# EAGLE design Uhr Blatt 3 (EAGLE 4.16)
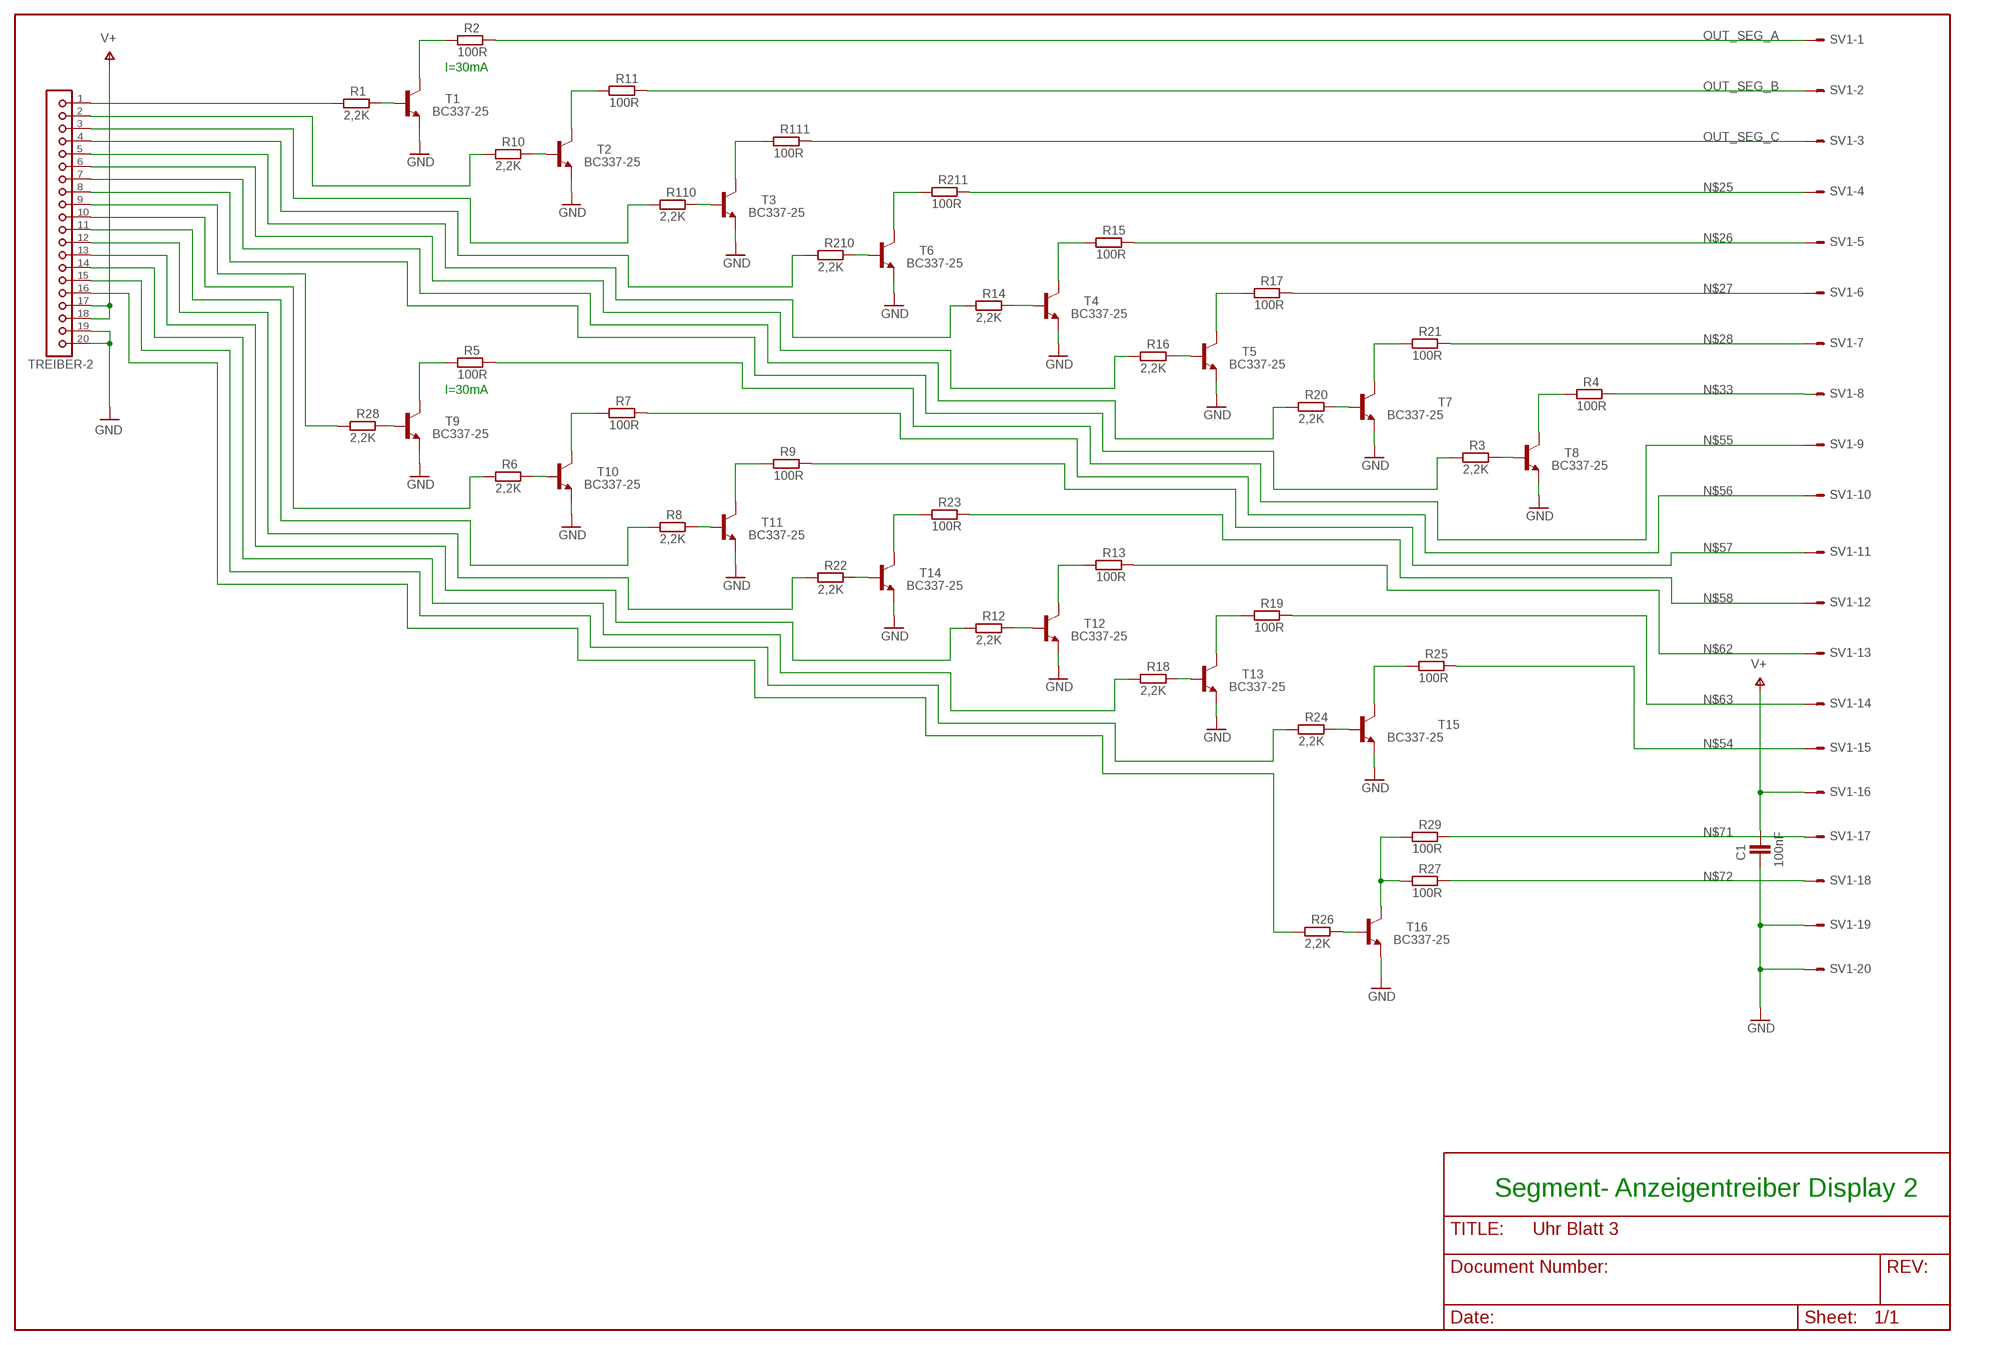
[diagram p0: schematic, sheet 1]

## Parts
C1  100nF  C-EU050-024X044  [C050-024X044]
R1  2,2K  R-EU_0207/10  [0207/10]
R2  100R  R-EU_0207/10  [0207/10]
R3  2,2K  R-EU_0207/10  [0207/10]
R4  100R  R-EU_0207/10  [0207/10]
R5  100R  R-EU_0207/10  [0207/10]
R6  2,2K  R-EU_0207/10  [0207/10]
R7  100R  R-EU_0207/10  [0207/10]
R8  2,2K  R-EU_0207/10  [0207/10]
R9  100R  R-EU_0207/10  [0207/10]
R10  2,2K  R-EU_0207/10  [0207/10]
R11  100R  R-EU_0207/10  [0207/10]
R12  2,2K  R-EU_0207/10  [0207/10]
R13  100R  R-EU_0207/10  [0207/10]
R14  2,2K  R-EU_0207/10  [0207/10]
R15  100R  R-EU_0207/10  [0207/10]
R16  2,2K  R-EU_0207/10  [0207/10]
R17  100R  R-EU_0207/10  [0207/10]
R18  2,2K  R-EU_0207/10  [0207/10]
R19  100R  R-EU_0207/10  [0207/10]
R20  2,2K  R-EU_0207/10  [0207/10]
R21  100R  R-EU_0207/10  [0207/10]
R22  2,2K  R-EU_0207/10  [0207/10]
R23  100R  R-EU_0207/10  [0207/10]
R24  2,2K  R-EU_0207/10  [0207/10]
R25  100R  R-EU_0207/10  [0207/10]
R26  2,2K  R-EU_0207/10  [0207/10]
R27  100R  R-EU_0207/10  [0207/10]
R28  2,2K  R-EU_0207/10  [0207/10]
R29  100R  R-EU_0207/10  [0207/10]
R110  2,2K  R-EU_0207/10  [0207/10]
R111  100R  R-EU_0207/10  [0207/10]
R210  2,2K  R-EU_0207/10  [0207/10]
R211  100R  R-EU_0207/10  [0207/10]
SV1  ML20E  [ML20]
T1  BC337-25  [TO92]
T2  BC337-25  [TO92]
T3  BC337-25  [TO92]
T4  BC337-25  [TO92]
T5  BC337-25  [TO92]
T6  BC337-25  [TO92]
T7  BC337-25  [TO92]
T8  BC337-25  [TO92]
T9  BC337-25  [TO92]
T10  BC337-25  [TO92]
T11  BC337-25  [TO92]
T12  BC337-25  [TO92]
T13  BC337-25  [TO92]
T14  BC337-25  [TO92]
T15  BC337-25  [TO92]
T16  BC337-25  [TO92]
TREIBER-2  JU20  [JU20]

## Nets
GND: C1.1 SV1.19 SV1.20 T1.1(E) T2.1(E) T3.1(E) T4.1(E) T5.1(E) T6.1(E) T7.1(E) T8.1(E) T9.1(E) T10.1(E) T11.1(E) T12.1(E) T13.1(E) T14.1(E) T15.1(E) T16.1(E) TREIBER-2.19 TREIBER-2.20
N$1: R2.1 T1.3(C)
N$2: R1.2 T1.2(B)
N$3: R11.1 T2.3(C)
N$4: R10.2 T2.2(B)
N$5: R111.1 T3.3(C)
N$6: R110.2 T3.2(B)
N$7: R15.1 T4.3(C)
N$8: R14.2 T4.2(B)
N$9: R17.1 T5.3(C)
N$10: R16.2 T5.2(B)
N$11: R211.1 T6.3(C)
N$12: R210.2 T6.2(B)
N$13: R21.1 T7.3(C)
N$14: R20.2 T7.2(B)
N$25: R211.2 SV1.4
N$26: R15.2 SV1.5
N$27: R17.2 SV1.6
N$28: R21.2 SV1.7
N$29: R4.1 T8.3(C)
N$30: R3.2 T8.2(B)
N$31: R5.1 T9.3(C)
N$33: R4.2 SV1.8
N$34: R7.1 T10.3(C)
N$35: R6.2 T10.2(B)
N$36: R9.1 T11.3(C)
N$37: R8.2 T11.2(B)
N$38: R13.1 T12.3(C)
N$39: R12.2 T12.2(B)
N$40: R19.1 T13.3(C)
N$41: R18.2 T13.2(B)
N$42: R23.1 T14.3(C)
N$43: R22.2 T14.2(B)
N$44: R25.1 T15.3(C)
N$45: R24.2 T15.2(B)
N$53: R28.2 T9.2(B)
N$54: R25.2 SV1.15
N$55: R5.2 SV1.9
N$56: R7.2 SV1.10
N$57: R9.2 SV1.11
N$58: R23.2 SV1.12
N$62: R13.2 SV1.13
N$63: R19.2 SV1.14
N$69: R26.2 T16.2(B)
N$70: R27.1 R29.1 T16.3(C)
N$71: R29.2 SV1.17
N$72: R27.2 SV1.18
OUT_SEG_A: R2.2 SV1.1
OUT_SEG_B: R11.2 SV1.2
OUT_SEG_C: R111.2 SV1.3
SEG_A: R1.1 TREIBER-2.1
SEG_B: R10.1 TREIBER-2.2
SEG_C: R110.1 TREIBER-2.3
SEG_D: R210.1 TREIBER-2.4
SEG_E+F: R26.1 TREIBER-2.16
SEG_G: R14.1 TREIBER-2.5
SEG_H: R16.1 TREIBER-2.6
SEG_I: R20.1 TREIBER-2.7
SEG_J: R3.1 TREIBER-2.8
SEG_K: R28.1 TREIBER-2.9
SEG_L: R6.1 TREIBER-2.10
SEG_M: R8.1 TREIBER-2.11
SEG_N: R22.1 TREIBER-2.12
SEG_O: R12.1 TREIBER-2.13
SEG_P: R18.1 TREIBER-2.14
SEG_X: R24.1 TREIBER-2.15
V+: C1.2 SV1.16 TREIBER-2.17 TREIBER-2.18

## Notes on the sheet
- I=30mA
- I=30mA
- Segment- | Anzeigentreiber Display 2

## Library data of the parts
C1 = rcl:C-EU: CAPACITOR, European symbol
R1-R29 R110 R111 R210 R211 = rcl:R-EU_: RESISTOR, European symbol
SV1 = con-harting-ml:ML20?E: HARTING
T1-T16 = transistor-npn:BC337*: NPN Transistor
TREIBER-2 = con-lsta:JU20: PIN HEADER

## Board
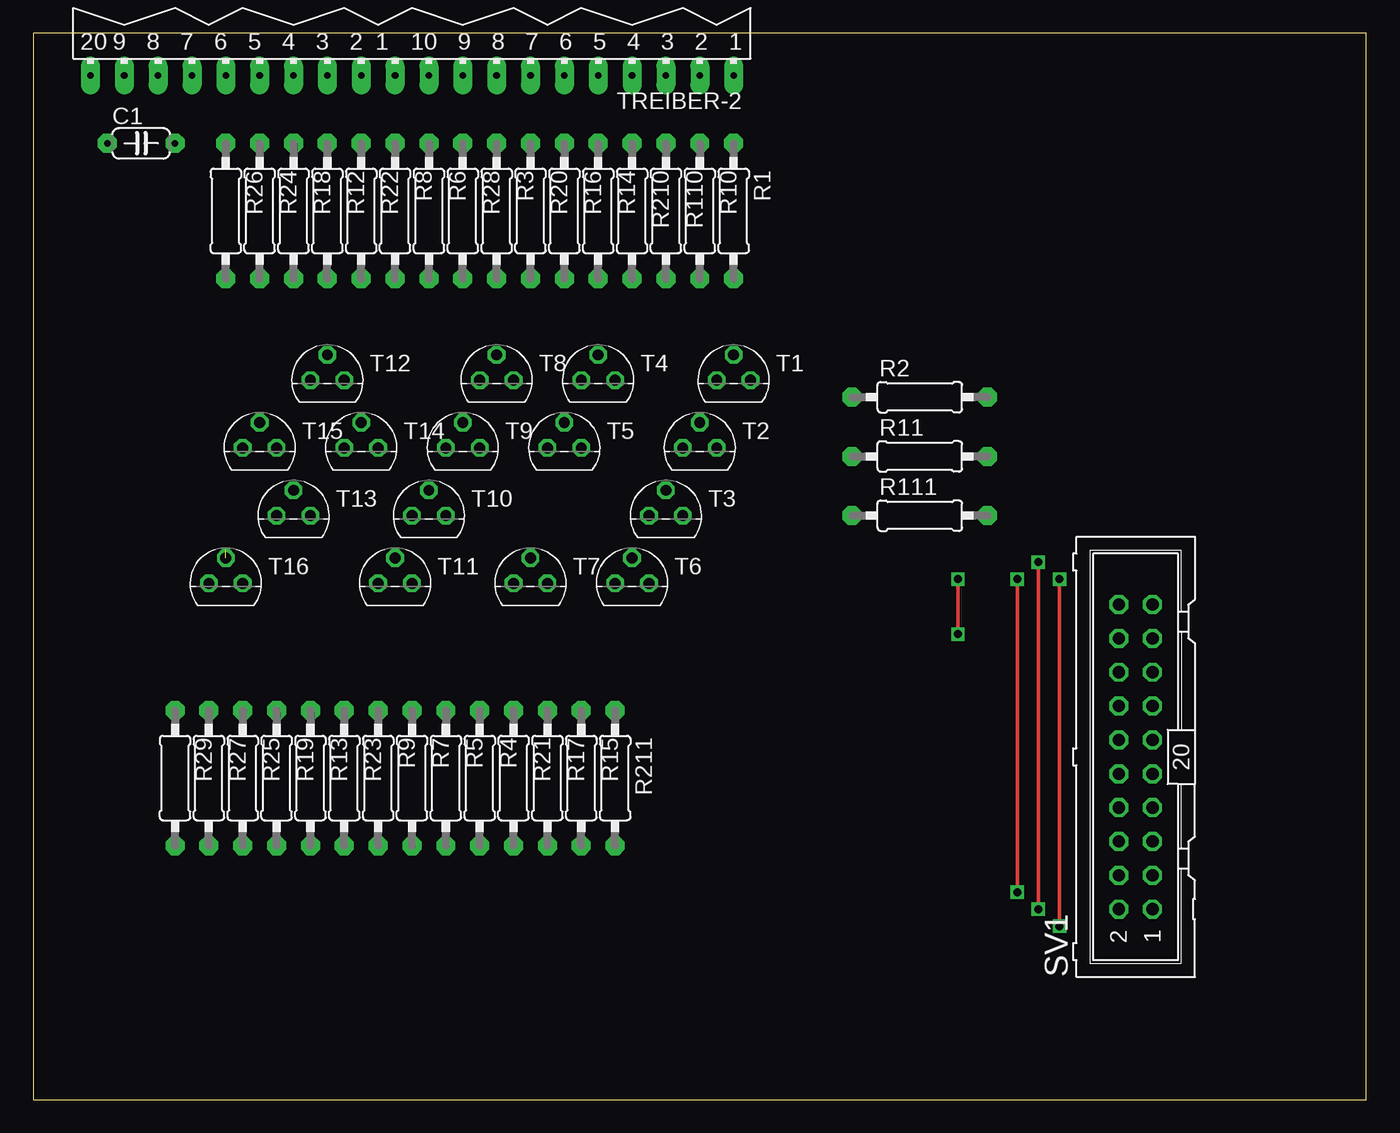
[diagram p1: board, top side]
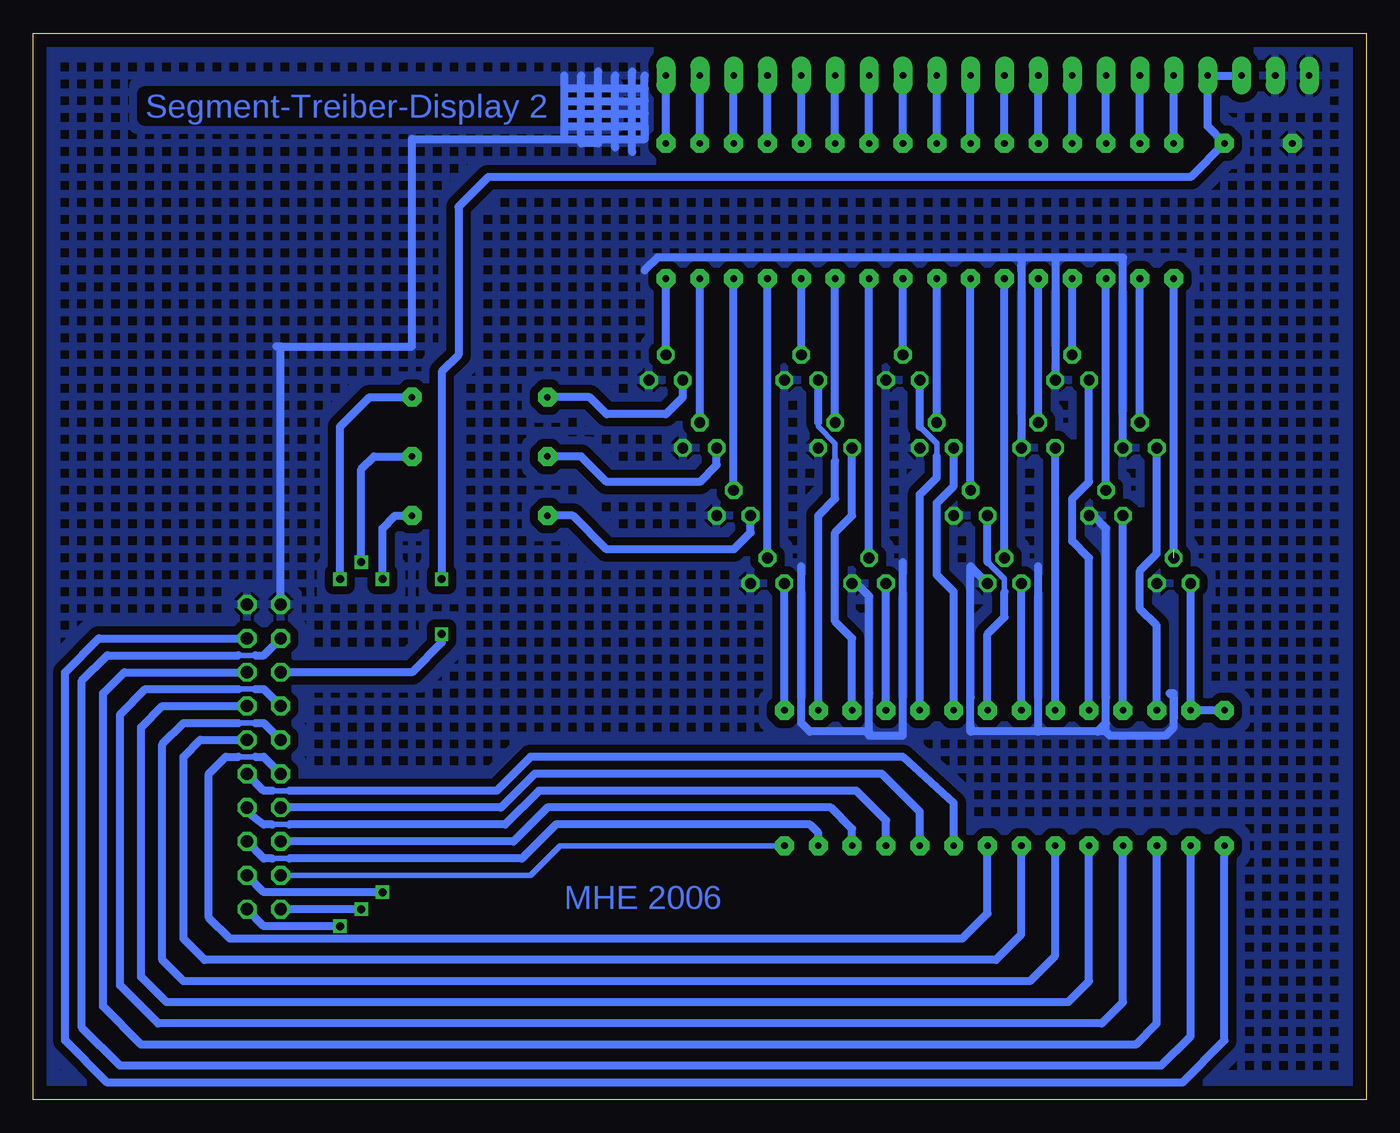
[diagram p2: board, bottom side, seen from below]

Size 100 x 80 mm. Coordinates in mm from the lower left corner, seen from the top.
Outline: 0,0 100,0 100,80 0,80 0,0
Copper layers (1*16): Top 0.035mm / dielectric 1.5mm / Bottom 0.035mm
Design rules "default": minimum track width 10mil, minimum drill 24mil, track to track 8mil, track to pad 8mil, pad to pad 8mil, via to via 8mil, smd to smd 8mil, copper to edge 40mil, drill to drill 8mil, minimum pad ring 10mil, minimum via ring 8mil, stop-mask expansion 4mil, vias tented up to drill 0mil, thermal gap 10mil

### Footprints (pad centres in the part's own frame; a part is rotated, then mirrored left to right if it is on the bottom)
C050-024X044 = drill 0.5 pad 1.422 octagon: 1 -2.54,0; 2 2.54,0
0207/10 = drill 0.5 pad 1.422 octagon: 1 -5.08,0; 2 5.08,0
ML20 = drill 0.914 octagon: 1 -11.43,-1.27; 2 -11.43,1.27; 3 -8.89,-1.27; 4 -8.89,1.27; 5 -6.35,-1.27; 6 -6.35,1.27; 7 -3.81,-1.27; 8 -3.81,1.27; 9 -1.27,-1.27; 10 -1.27,1.27; 11 1.27,-1.27; 12 1.27,1.27; 13 3.81,-1.27; 14 3.81,1.27; 15 6.35,-1.27; 16 6.35,1.27; 17 8.89,-1.27; 18 8.89,1.27; 19 11.43,-1.27; 20 11.43,1.27
TO92 = drill 0.813 octagon: 1 1.27,0; 2 0,1.905; 3 -1.27,0
JU20 = drill 0.5 pad 1.422 long: 1 -24.13,0; 2 -21.59,0; 3 -19.05,0; 4 -16.51,0; 5 -13.97,0; 6 -11.43,0; 7 -8.89,0; 8 -6.35,0; 9 -3.81,0; 10 -1.27,0; 11 1.27,0; 12 3.81,0; 13 6.35,0; 14 8.89,0; 15 11.43,0; 16 13.97,0; 17 16.51,0; 18 19.05,0; 19 21.59,0; 20 24.13,0

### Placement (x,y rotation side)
C1  8.09,71.75 0 top
R1  52.54,66.67 270 top
R2  66.51,52.7 0 top
R3  34.76,66.67 270 top
R4  33.49,24.12 270 top
R5  30.95,24.12 270 top
R6  29.68,66.67 270 top
R7  28.41,24.12 270 top
R8  27.14,66.67 270 top
R9  25.87,24.12 270 top
R10  50,66.67 270 top
R11  66.51,48.26 0 top
R12  22.06,66.67 270 top
R13  20.79,24.12 270 top
R14  42.38,66.67 270 top
R15  41.11,24.12 270 top
R16  39.84,66.67 270 top
R17  38.57,24.12 270 top
R18  19.52,66.67 270 top
R19  18.25,24.12 270 top
R20  37.3,66.67 270 top
R21  36.03,24.12 270 top
R22  24.6,66.67 270 top
R23  23.33,24.12 270 top
R24  16.98,66.67 270 top
R25  15.71,24.12 270 top
R26  14.44,66.67 270 top
R27  13.17,24.12 270 top
R28  32.22,66.67 270 top
R29  10.63,24.12 270 top
R110  47.46,66.67 270 top
R111  66.51,43.81 0 top
R210  44.92,66.67 270 top
R211  43.65,24.12 270 top
SV1  82.7,25.71 90 top
T1  52.54,53.97 0 top
T2  50,48.89 0 top
T3  47.46,43.81 0 top
T4  42.38,53.97 0 top
T5  39.84,48.89 0 top
T6  44.92,38.73 0 top
T7  37.3,38.73 0 top
T8  34.76,53.97 0 top
T9  32.22,48.89 0 top
T10  29.68,43.81 0 top
T11  27.14,38.73 0 top
T12  22.06,53.97 0 top
T13  19.52,43.81 0 top
T14  24.6,48.89 0 top
T15  16.98,48.89 0 top
T16  14.44,38.73 0 top
TREIBER-2  28.41,76.83 180 top

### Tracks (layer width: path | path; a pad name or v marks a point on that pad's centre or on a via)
GND
  Bottom 0.61: 14.44,30.16 14.44,30.47 14.76,30.47 14.44,30.16 | 14.44,30.16 14.44,28.57 | 42.38,40 42.38,28.25 41.74,27.62 37.3,27.62 | 25.87,62.23 T14.1 | 25.87,62.23 25.87,62.54 | 34.76,40.32 34.76,27.3 37.3,27.3 37.3,27.62 | 37.3,27.62 37.3,30.47 | 19.52,27.62 19.52,30.16 | 19.52,27.62 20.15,27.62 | 20.15,27.62 24.6,27.62 | 24.6,27.62 24.6,40 | 24.6,27.62 29.68,27.62 29.68,27.93 | 29.68,27.93 29.68,30.16 | T15.1 18.25,63.18 23.33,63.18 | 23.33,63.18 T12.1 | 23.33,63.18 25.87,63.18 | 25.87,63.18 25.87,62.23 | 14.44,30.16 14.44,27.93 15.08,27.3 19.2,27.3 19.52,27.62 | T13.1 20.47,43.81 19.52,42.86 19.52,28.25 20.15,27.62 | T11.1 29.68,40 29.68,27.93 | T7.1 38.25,38.73 37.3,37.78 37.3,27.62 | 54.13,73.02 54.13,72.07 58.89,72.07 | 54.13,73.02 54.13,73.97 | 54.13,73.97 54.13,74.92 | 54.13,74.92 54.13,75.88 | 54.13,75.88 54.13,76.83 | 25.87,63.18 53.17,63.18 54.13,62.23 | 60.16,72.07 71.59,72.07 71.59,56.51 81.43,56.51 | 60.16,72.07 58.89,72.07 | 81.43,56.51 81.75,56.51 | SV1.20 81.43,56.51 | 55.08,71.11 55.08,77.15 | 58.89,72.07 58.89,76.83 | 60.16,72.07 60.16,73.02 | 60.16,73.02 60.16,73.97 | 60.16,73.97 60.16,74.92 | 60.16,74.92 60.16,75.88 | 60.16,75.88 60.16,76.83 | 60.16,75.88 54.13,75.88 | 60.16,74.92 54.13,74.92 | 60.16,73.97 54.13,73.97 | 60.16,73.02 54.13,73.02 | 56.35,71.43 56.35,76.83 | 57.62,77.15 57.62,71.75 58.89,71.75 58.89,72.07
  pour Bottom (isolate 0.61, hatched): 0.47,0.63 0.47,79.37 99.85,79.37 99.85,0.63
N$1
  Bottom 0.61: T1.3 51.27,52.7 52.54,51.43 56.98,51.43 58.25,52.7 R2.1
N$2
  Bottom 0.61: T1.2 R1.2
N$3
  Bottom 0.61: T2.3 48.73,47.62 50,46.35 56.98,46.35 58.89,48.26 R11.1
N$4
  Bottom 0.61: T2.2 R10.2
N$5
  Bottom 0.61: T3.3 46.19,42.54 47.46,41.27 56.98,41.27 59.52,43.81 R111.1
N$6
  Bottom 0.61: T3.2 R110.2
N$7
  Bottom 0.406: 41.11,50.8 41.11,50.48 39.84,49.21 39.84,47.94
  Bottom 0.61: 41.11,51.11 T4.3 | 41.11,50.8 41.11,51.11 | 39.84,47.94 39.84,45.08 41.11,43.81 R15.1 | 41.11,51.11 41.11,54.29
N$8
  Bottom 0.61: T4.2 R14.2
N$9
  Bottom 0.61: T5.3 38.57,43.81 39.84,42.54 39.84,35.87 38.57,34.6 R17.1
N$10
  Bottom 0.61: T5.2 R16.2
N$11
  Bottom 0.61: R211.1 T6.3
N$12
  Bottom 0.61: T6.2 R210.2
N$13
  Bottom 0.61: R21.1 T7.3
N$14
  Bottom 0.61: T7.2 R20.2
N$25
  Bottom 0.406: R211.2 60.48,19.04 62.7,16.82 SV1.4
N$26
  Bottom 0.406: 80.8,18.09 82.07,18.09
  Bottom 0.61: R15.2 41.11,20 41.74,20.63 60.8,20.63 63.34,18.09 80.8,18.09 | 82.07,18.09 82.7,18.09 SV1.5
N$27
  Bottom 0.61: R17.2 38.57,20.31 40.16,21.9 61.43,21.9 63.97,19.36 SV1.6
N$28
  Bottom 0.406: 80.8,20.63 82.07,20.63
  Bottom 0.61: R21.2 36.03,20.95 38.25,23.17 62.06,23.17 64.61,20.63 80.8,20.63 | SV1.7 83.97,21.58 82.7,20.63 82.07,20.63
N$29
  Bottom 0.406: 33.49,50.48 32.22,49.21 32.22,48.26
  Bottom 0.61: 33.49,50.48 T8.3 | 32.22,48.26 32.22,46.67 33.49,45.4 R4.1
N$30
  Bottom 0.61: T8.2 R3.2
N$31
  Bottom 0.61: T9.3 30.95,46.03 32.22,44.76 32.22,39.37 30.95,38.1 R5.1
N$33
  Bottom 0.61: R4.2 33.49,21.58 36.35,24.44 62.38,24.44 64.92,21.9 SV1.8
N$34
  Bottom 0.406: 28.41,40.32 27.14,39.05 27.14,38.1
  Bottom 0.61: 28.41,40.32 T10.3 | 27.14,38.1 27.14,36.19 28.41,34.92 R7.1
N$35
  Bottom 0.61: T10.2 R6.2
N$36
  Bottom 0.61: R9.1 T11.3
N$37
  Bottom 0.61: T11.2 R8.2
N$38
  Bottom 0.61: T12.3 20.79,46.35 22.06,45.08 22.06,41.91 20.79,40.64 R13.1
N$39
  Bottom 0.61: T12.2 R12.2
N$40
  Bottom 0.61: R19.1 T13.3
N$41
  Bottom 0.61: T13.2 R18.2
N$42
  Bottom 0.61: R23.1 T14.3
N$43
  Bottom 0.61: T14.2 R22.2
N$44
  Bottom 0.61: T15.3 15.71,40.95 16.98,39.68 16.98,36.83 15.71,35.55 R25.1
N$45
  Bottom 0.61: T15.2 R24.2
N$53
  Bottom 0.61: T9.2 R28.2
N$54
  Bottom 0.61: R25.2 15.71,5.71 17.3,4.12 91.91,4.12 94.77,6.98 94.77,30.47 93.18,32.06 SV1.15
N$55
  Bottom 0.406: 80.8,23.17 82.07,23.17
  Bottom 0.61: R5.2 30.95,22.22 34.76,25.71 62.7,25.71 65.24,23.17 80.8,23.17 | 82.07,23.17 82.7,23.17 SV1.9
N$56
  Bottom 0.406: 84.61,25.71 83.34,25.71
  Bottom 0.61: R7.2 28.41,13.97 30.31,12.06 85.24,12.06 86.83,13.65 86.83,24.44 85.56,25.71 84.61,25.71 | SV1.10 82.7,25.71 83.34,25.71
N$57
  Bottom 0.61: R9.2 25.87,12.38 27.77,10.47 87.15,10.47 88.73,12.06 88.73,25.71 87.47,26.98 SV1.11
N$58
  Bottom 0.406: 84.61,28.25 83.34,28.25
  Bottom 0.61: R23.2 23.33,10.79 25.23,8.89 88.73,8.89 90.32,10.47 90.32,26.66 88.73,28.25 84.61,28.25 | SV1.12 82.7,28.25 83.34,28.25
N$62
  Bottom 0.61: R13.2 20.79,8.89 22.38,7.3 90,7.3 91.91,9.2 91.91,27.93 90.32,29.52 SV1.13
N$63
  Bottom 0.406: 84.61,30.79 83.34,30.79
  Bottom 0.61: R19.2 18.25,7.3 19.84,5.71 90.64,5.71 93.5,8.57 93.5,28.89 91.59,30.79 84.61,30.79 | SV1.14 82.7,30.79 83.34,30.79
N$69  (1 unrouted)
  Bottom 0.61: 14.44,41.27 R26.2
N$70
  Bottom 0.61: T16.3 R27.1 R29.1
N$71
  Bottom 0.61: R29.2 10.63,4.44 13.81,1.27 94.45,1.27 97.62,4.44 97.62,32.06 95.08,34.6 SV1.17
N$72
  Bottom 0.406: 84.61,33.33 83.34,33.33
  Bottom 0.61: R27.2 13.17,4.76 15.39,2.54 93.5,2.54 96.36,5.39 96.36,31.43 94.45,33.33 84.61,33.33 | SV1.18 82.7,33.33 83.34,33.33
OUT_SEG_A  (via drill 0.6)
  Top 0.254: v76.99,13.01 v76.99,39.05
  Bottom 0.61: R2.2 74.77,52.7 76.99,50.48 v76.99,39.05 | v76.99,13.01 82.7,13.01 SV1.1
OUT_SEG_B  (via drill 0.6)
  Top 0.254: v75.4,14.28 v75.4,40.32
  Bottom 0.61: R11.2 74.45,48.26 75.4,47.3 v75.4,40.32 | v75.4,14.28 SV1.2
OUT_SEG_C  (via drill 0.6)
  Top 0.254: v73.81,15.55 v73.81,39.05
  Bottom 0.61: R111.2 72.86,43.81 73.81,42.86 v73.81,39.05 | v73.81,15.55 82.7,15.55 SV1.3
SEG_A
  Bottom 0.61: R1.1 TREIBER-2.1
SEG_B
  Bottom 0.61: R10.1 TREIBER-2.2
SEG_C
  Bottom 0.61: R110.1 TREIBER-2.3
SEG_D
  Bottom 0.61: R210.1 TREIBER-2.4
SEG_E+F
  Bottom 0.61: R26.1 TREIBER-2.16
SEG_G
  Bottom 0.61: R14.1 TREIBER-2.5
SEG_H
  Bottom 0.61: R16.1 TREIBER-2.6
SEG_I
  Bottom 0.61: R20.1 TREIBER-2.7
SEG_J
  Bottom 0.61: R3.1 TREIBER-2.8
SEG_K
  Bottom 0.61: R28.1 TREIBER-2.9
SEG_L
  Bottom 0.61: R6.1 TREIBER-2.10
SEG_M
  Bottom 0.61: R8.1 TREIBER-2.11
SEG_N
  Bottom 0.61: R22.1 TREIBER-2.12
SEG_O
  Bottom 0.61: R12.1 TREIBER-2.13
SEG_P
  Bottom 0.61: R18.1 TREIBER-2.14
SEG_X
  Bottom 0.61: R24.1 TREIBER-2.15
V+  (via drill 0.6)
  Top 0.254: v69.37,39.05 v69.37,34.92
  Bottom 0.61: TREIBER-2.18 TREIBER-2.17 11.9,73.02 C1.2 13.17,69.21 65.88,69.21 68.1,66.99 68.1,55.88 69.37,54.61 69.37,40 v69.37,39.05 | SV1.16 71.59,32.06 69.37,34.29 v69.37,34.92

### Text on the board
Bottom: Segment-Treiber-Display 2 | MHE 2006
